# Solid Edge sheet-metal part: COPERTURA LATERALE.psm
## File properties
Subject: COPERTURA LATERALE
Author: f_grande
Template: Normal.psm
Last saved by: f_grande
Revision: 1
Application: Solid Edge
Document Number: KR0500
Density: 1385,000 kg/m^3
Accuracy: 0,990
Material Thickness: 4,00 mm
Bend Radius: 1,00 mm
Relief Width: 1,00 mm
Relief Length: 0,00 mm
Neutral Factor: 0,330
Minimum Arc Length: 0,10 mm
Deviational Tolerance: 0,10 mm
Tipo di contenuto documento: 0
Material: Plexiglas trasparente
Stile della faccia: Bianco (vetro)
Stile di riempimento: ANSI34(Plastica)
Stile virtuale: Marroncino (lucido)
Coef. of Thermal Exp: 0.0
Thermal Conductivity: 1.5
Specific Heat: 0.0
Modulus of Elasticity: 2757902.8
Poisson's Ratio: 0.4
Yield Stress: 6894757.0
Ultimate Stress: 0.0
Elongation: 0.0
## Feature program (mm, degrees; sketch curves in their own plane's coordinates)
base tab "unnamed BaseTab 1"
flange "Lembo_1"
flange "Lembo_2"
sketch for "Foro_1" plane through (0, -29.5, -100) normal (0, 0, -1) x-axis (1, 0, 0)
  hole centre (-465, 0) bore radius 2.5
hole "Foro_1"
sketch for "unnamed Hole 1" plane through (0, -29.5, -100) normal (0, 0, -1) x-axis (1, 0, 0)
  hole centre (465, 0) bore radius 2.5
hole "unnamed Hole 1"
pattern "unnamed Pattern 1" of "Foro_1", "unnamed Hole 1"
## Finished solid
Body 1: solid body, 16 faces, 40 edges, 24 vertices.
  Faces by surface: plane 10, cylinder 6
  Edges by curve: line 28, circle 12
Bounding box of the edges (mm): 1050.000 x 54.000 x 200.000, from (-525, -54, -100) to (525, 0, 100).
Cylindrical faces by radius (mm): R1 x2, R2.5 x2, R5 x2
Planar faces by outward normal: +x 1, +y 1, +z 2, -x 1, -y 3, -z 2
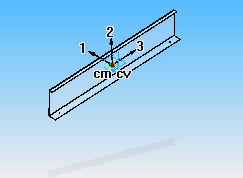
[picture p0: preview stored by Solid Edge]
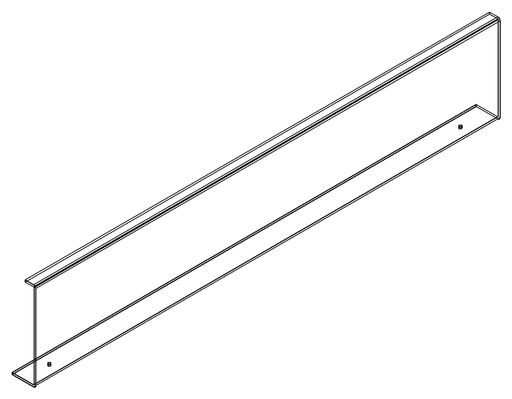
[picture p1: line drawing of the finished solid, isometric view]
